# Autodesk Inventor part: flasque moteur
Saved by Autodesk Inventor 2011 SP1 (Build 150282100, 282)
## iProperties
Created: 2010-12
Part Number: flasque moteur
Document SubType Name: Modeling
Designer: eric
Density: 1 g/cm^3
Author: eric
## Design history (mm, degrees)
feature "Base1"
node "Solide1"
node "Corps solides"
node "Corps surfaciques"
